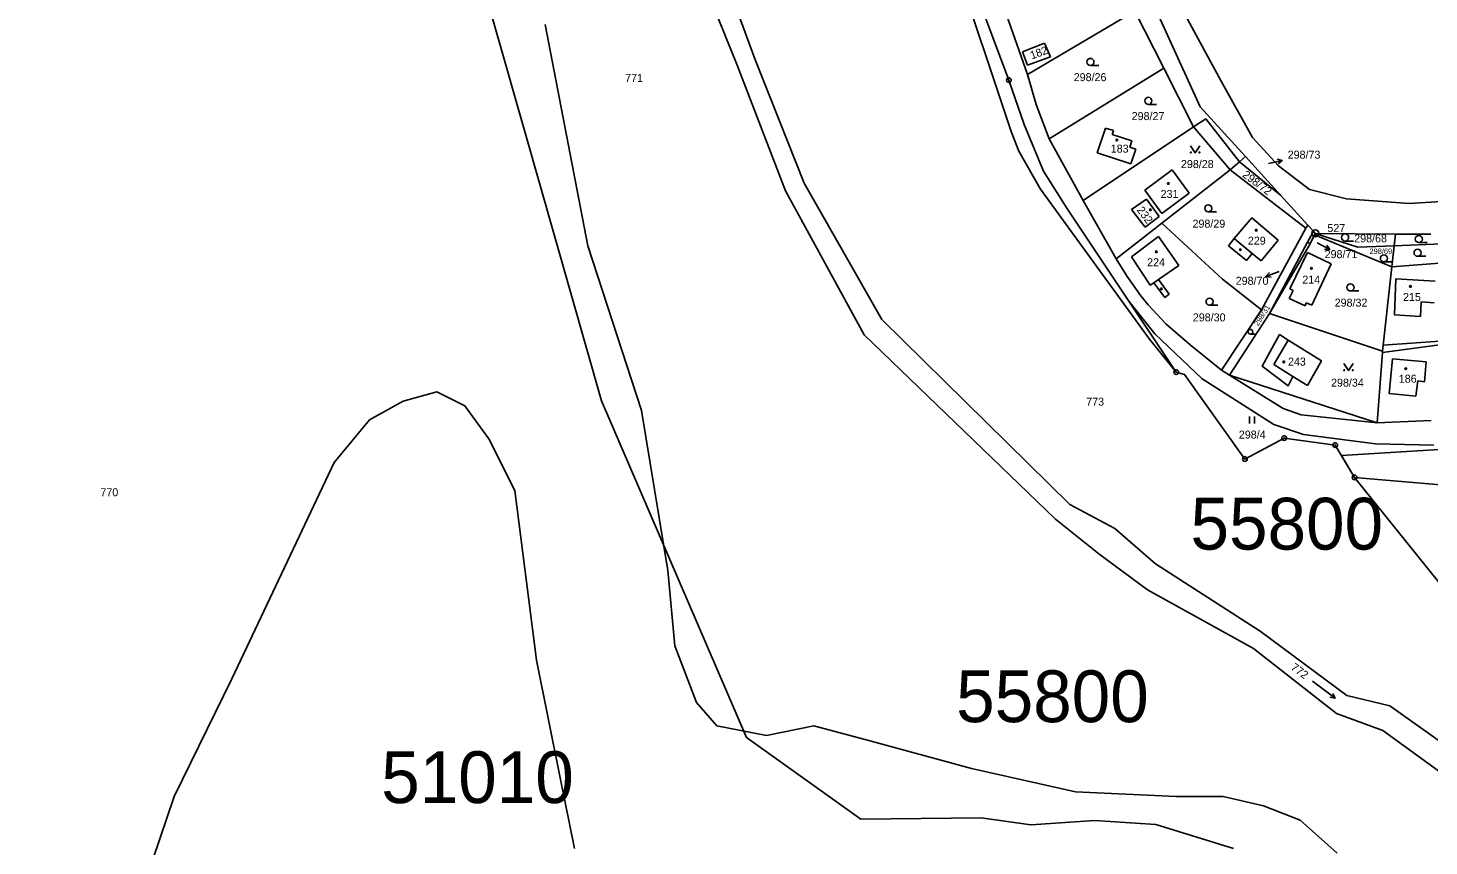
# Model space of a CAD drawing. Extents: x -725765 to -723182, y -1052705 to -1049154.
# Drawn here: x -724049.7 to -723752.1, y -1051559.5 to -1051385.7 of the extents above; entities that cross this region are included whole.
import ezdxf

# ---------------------------------------------------------------- set-up
doc = ezdxf.new("R2010")
doc.units = 0
for name, color, linetype in [('Vrstva 1', 7, 'Continuous'), ('Vrstva 16', 7, 'Continuous'), ('Vrstva 17', 7, 'Continuous'), ('Vrstva 18', 7, 'Continuous'), ('Vrstva 19', 7, 'Continuous'), ('Vrstva 25', 7, 'Continuous'), ('Vrstva 4', 7, 'Continuous'), ('Vrstva 52', 7, 'Continuous'), ('Vrstva 53', 7, 'Continuous')]:
    doc.layers.add(name, color=color, linetype=linetype)

msp = doc.modelspace()

# ---------------------------------------------------------------- linework, layer by layer
at = {"layer": 'Vrstva 1'}
for points in [[(-723911.42, -1051348.47), (-723895.29, -1051392.3)], [(-723825.2, -1051348.64), (-723800.75, -1051402.47)], [(-723899.09, -1051393.61), (-723916.43, -1051350.67)], [(-723841.35, -1051396.8), (-723855.41, -1051359.31)], [(-723944.12, -1051407.98), (-723956.41, -1051364.73)], [(-723853.14, -1051370.95), (-723840.86, -1051407.69)], [(-723844.1, -1051376.44), (-723837.44, -1051395.61)], [(-723837.44, -1051395.61), (-723814.6, -1051382.17)], [(-723814.6, -1051382.17), (-723808.48, -1051394.25)], [(-723838.46, -1051390.82), (-723833.78, -1051388.96)], [(-723833.78, -1051388.96), (-723832.5, -1051391.88)], [(-723895.29, -1051392.3), (-723884.86, -1051418.68)], [(-723838.46, -1051390.82), (-723837.38, -1051393.6)], [(-723837.38, -1051393.6), (-723832.5, -1051391.88)], [(-723888.79, -1051420.29), (-723899.09, -1051393.61)], [(-723837.44, -1051395.61), (-723835.54, -1051402)], [(-723832.83, -1051409.25), (-723808.48, -1051394.25)], [(-723808.48, -1051394.25), (-723802.14, -1051406.75)], [(-723838.11, -1051406.2), (-723841.35, -1051396.8)], [(-723835.54, -1051402), (-723832.83, -1051409.25)], [(-723800.75, -1051402.47), (-723791.11, -1051413.06)], [(-723927.86, -1051464.93), (-723944.12, -1051407.98)], [(-723839.23, -1051411.86), (-723840.86, -1051407.69)], [(-723834.01, -1051416.11), (-723838.11, -1051406.2)], [(-723825.55, -1051422.36), (-723802.14, -1051406.75)], [(-723822.62, -1051412.25), (-723820.86, -1051406.99)], [(-723820.86, -1051406.99), (-723819.12, -1051407.53)], [(-723819.39, -1051408.38), (-723819.12, -1051407.53)], [(-723802.14, -1051406.75), (-723794.39, -1051415.85)], [(-723832.83, -1051409.25), (-723825.55, -1051422.36)], [(-723819.39, -1051408.38), (-723815.24, -1051409.7)], [(-723815.65, -1051411.04), (-723815.24, -1051409.7)], [(-723815.65, -1051411.04), (-723814.42, -1051411.46)], [(-723834.66, -1051419.95), (-723839.23, -1051411.86)], [(-723822.62, -1051412.25), (-723815.48, -1051414.58)], [(-723815.48, -1051414.58), (-723814.42, -1051411.46)], [(-723792.39, -1051414.15), (-723794.39, -1051415.85)], [(-723791.11, -1051413.06), (-723792.39, -1051414.15)], [(-723792.39, -1051414.15), (-723783.68, -1051421.23)], [(-723791.11, -1051413.06), (-723783.68, -1051421.23)], [(-723829.05, -1051424.03), (-723834.01, -1051416.11)], [(-723812.51, -1051420.19), (-723806.67, -1051415.85)], [(-723808.88, -1051427.21), (-723794.39, -1051415.85)], [(-723806.67, -1051415.85), (-723803.04, -1051420.8)], [(-723794.39, -1051415.85), (-723778.28, -1051428.28)], [(-723868.34, -1051447.67), (-723884.86, -1051418.68)], [(-723811.53, -1051451.84), (-723834.66, -1051419.95)], [(-723812.51, -1051420.19), (-723808.88, -1051425.14)], [(-723872.12, -1051450.91), (-723888.79, -1051420.29)], [(-723825.55, -1051422.36), (-723818.59, -1051434.75)], [(-723815.3, -1051424.29), (-723812.11, -1051422.11)], [(-723812.11, -1051422.11), (-723809.41, -1051425.77)], [(-723808.88, -1051425.14), (-723803.04, -1051420.8)], [(-723783.68, -1051421.23), (-723777.9, -1051427.58)], [(-723829.05, -1051424.03), (-723815.9, -1051443.73)], [(-723815.3, -1051424.29), (-723812.43, -1051428.06)], [(-723812.43, -1051428.06), (-723809.41, -1051425.77)], [(-723793.5, -1051430.44), (-723789.79, -1051426.05)], [(-723789.79, -1051426.05), (-723784.18, -1051430.79)], [(-723818.59, -1051434.75), (-723808.88, -1051427.21)], [(-723808.88, -1051427.21), (-723795.99, -1051439.08)], [(-723787.69, -1051445.63), (-723778.28, -1051428.28)], [(-723777.9, -1051427.58), (-723778.28, -1051428.28)], [(-723777.9, -1051427.58), (-723776.69, -1051428.91)], [(-723776.69, -1051428.91), (-723776.9, -1051429.34)], [(-723776.69, -1051428.91), (-723776.29, -1051429.35)], [(-723815.35, -1051434.34), (-723809.58, -1051429.99)], [(-723809.58, -1051429.99), (-723805.28, -1051436.16)], [(-723794.7, -1051431.98), (-723793.5, -1051430.44)], [(-723794.7, -1051431.98), (-723790.93, -1051435.13)], [(-723787.79, -1051435.2), (-723784.18, -1051430.79)], [(-723777.93, -1051431.25), (-723785.99, -1051446.36)], [(-723785.99, -1051446.36), (-723777.34, -1051431.57)], [(-723776.9, -1051429.34), (-723777.93, -1051431.25)], [(-723777.34, -1051431.57), (-723777.93, -1051431.25)], [(-723776.45, -1051429.69), (-723777.34, -1051431.57)], [(-723776.29, -1051429.35), (-723776.45, -1051429.69)], [(-723776.45, -1051429.69), (-723760.04, -1051436.48)], [(-723776.29, -1051429.35), (-723759.26, -1051429.49)], [(-723776.29, -1051429.35), (-723767.23, -1051432.28)], [(-723767.23, -1051432.28), (-723759.54, -1051431.99)], [(-723759.54, -1051431.99), (-723760.04, -1051436.48)], [(-723759.26, -1051429.49), (-723759.54, -1051431.99)], [(-723759.54, -1051431.99), (-723749.44, -1051431.61)], [(-723759.26, -1051429.49), (-723751.73, -1051429.55)], [(-723818.59, -1051434.75), (-723816.25, -1051438.54)], [(-723815.35, -1051434.34), (-723811.32, -1051440.39)], [(-723790.93, -1051435.13), (-723789.68, -1051433.63)], [(-723789.68, -1051433.63), (-723787.79, -1051435.2)], [(-723781.68, -1051441.15), (-723777.97, -1051433.39)], [(-723777.97, -1051433.39), (-723772.88, -1051435.83)], [(-723760.04, -1051436.48), (-723736.13, -1051434.61)], [(-723809.57, -1051439.17), (-723805.28, -1051436.16)], [(-723777.02, -1051444.64), (-723772.88, -1051435.83)], [(-723761.87, -1051453.08), (-723760.04, -1051436.48)], [(-723816.25, -1051438.54), (-723813.33, -1051442.65)], [(-723811.32, -1051440.39), (-723810.6, -1051439.89)], [(-723810.6, -1051439.89), (-723808.27, -1051443.01)], [(-723809.57, -1051439.17), (-723807.3, -1051442.3)], [(-723795.99, -1051439.08), (-723787.69, -1051445.63)], [(-723759.45, -1051446.66), (-723759.19, -1051439.04)], [(-723759.19, -1051439.04), (-723750.8, -1051439.52)], [(-723815.9, -1051443.73), (-723810.33, -1051450.69)], [(-723815.9, -1051443.73), (-723805.81, -1051458.83)], [(-723813.33, -1051442.65), (-723811.81, -1051444.52)], [(-723808.27, -1051443.01), (-723807.3, -1051442.3)], [(-723781.81, -1051443.16), (-723781, -1051441.47)], [(-723781.81, -1051443.16), (-723778.47, -1051444.73)], [(-723781.68, -1051441.15), (-723781, -1051441.47)], [(-723753.96, -1051446.99), (-723753.78, -1051443.91)], [(-723753.78, -1051443.91), (-723751.05, -1051444.1)], [(-723811.81, -1051444.52), (-723808.03, -1051448.54)], [(-723796.17, -1051458.45), (-723787.69, -1051445.63)], [(-723794.52, -1051459.51), (-723785.99, -1051446.36)], [(-723785.99, -1051446.36), (-723762.01, -1051454.37)], [(-723778.47, -1051444.73), (-723778.19, -1051444.09)], [(-723778.19, -1051444.09), (-723777.02, -1051444.64)], [(-723759.45, -1051446.66), (-723753.96, -1051446.99)], [(-723828.41, -1051486.92), (-723868.34, -1051447.67)], [(-723808.03, -1051448.54), (-723802.85, -1051453.06)], [(-723831.46, -1051490.09), (-723872.12, -1051450.91)], [(-723811.53, -1051451.84), (-723805.81, -1051458.83)], [(-723810.33, -1051450.69), (-723800.28, -1051460.26)], [(-723781.05, -1051459.74), (-723782.03, -1051461.72), (-723787.55, -1051457.58), (-723783.87, -1051450.86), (-723782.02, -1051452.02)], [(-723782.02, -1051452.02), (-723774.97, -1051456.43), (-723777.96, -1051461.66)], [(-723761.87, -1051453.08), (-723737.77, -1051451.4)], [(-723802.85, -1051453.06), (-723796.17, -1051458.45)], [(-723763.16, -1051469.61), (-723762.03, -1051454.69)], [(-723762.03, -1051454.69), (-723762.01, -1051454.37)], [(-723762.01, -1051454.37), (-723761.87, -1051453.08)], [(-723804.04, -1051459.34), (-723805.81, -1051458.83)], [(-723796.17, -1051458.45), (-723794.52, -1051459.51)], [(-723760.63, -1051463.39), (-723759.92, -1051456)], [(-723759.92, -1051456), (-723752.75, -1051456.65)], [(-723753.12, -1051460.88), (-723752.75, -1051456.65)], [(-723791.24, -1051477.29), (-723804.04, -1051459.34)], [(-723800.28, -1051460.26), (-723785.11, -1051469.97)], [(-723794.52, -1051459.51), (-723763.16, -1051469.61)], [(-723777.96, -1051461.66), (-723781.05, -1051459.74)], [(-723754.9, -1051463.94), (-723754.51, -1051460.71)], [(-723754.51, -1051460.71), (-723753.12, -1051460.88)], [(-723760.63, -1051463.39), (-723754.9, -1051463.94)], [(-723927.86, -1051464.93), (-723897.11, -1051536.45)], [(-723785.11, -1051469.97), (-723778.79, -1051472.11)], [(-723763.16, -1051469.61), (-723751.71, -1051469.1)], [(-723782.91, -1051472.84), (-723791.24, -1051477.29)], [(-723782.91, -1051472.84), (-723772.04, -1051474.32)], [(-723778.79, -1051472.11), (-723763.53, -1051474.03)], [(-723767.94, -1051481.2), (-723772.04, -1051474.32)], [(-723770.72, -1051476.53), (-723730.31, -1051474.06)], [(-723770.72, -1051476.53), (-723767.94, -1051481.2)], [(-723763.53, -1051474.03), (-723751.13, -1051474.35)], [(-723767.94, -1051481.2), (-723745.73, -1051508.83)], [(-723706.54, -1051486.44), (-723767.94, -1051481.2)], [(-723818.84, -1051492.05), (-723828.41, -1051486.92)], [(-723822.26, -1051497.46), (-723831.46, -1051490.09)], [(-723810.19, -1051499.57), (-723818.84, -1051492.05)], [(-723811.9, -1051505.06), (-723822.26, -1051497.46)], [(-723787.98, -1051513.89), (-723810.19, -1051499.57)], [(-723789.38, -1051517.54), (-723811.9, -1051505.06)], [(-723769.62, -1051527.53), (-723787.98, -1051513.89)], [(-723771.8, -1051531.34), (-723789.38, -1051517.54)], [(-723760.44, -1051529.74), (-723769.62, -1051527.53)], [(-723735.81, -1051547.23), (-723760.44, -1051529.74)], [(-723761.92, -1051534.99), (-723771.8, -1051531.34)], [(-723738.43, -1051552.03), (-723761.92, -1051534.99)], [(-723897.11, -1051536.45), (-723872.8, -1051553.77)], [(-723872.8, -1051553.77), (-723847.23, -1051553.49)], [(-723847.23, -1051553.49), (-723836.69, -1051554.99)], [(-723836.69, -1051554.99), (-723823.11, -1051554.09)], [(-723823.11, -1051554.09), (-723810.14, -1051554.93)], [(-723810.14, -1051554.93), (-723793.66, -1051560.02)]]:
    msp.add_lwpolyline(points, dxfattribs=at)
at = {"layer": 'Vrstva 25'}
for points in [[(-723824.04, -1051393.68), (-723822.29, -1051393.68)], [(-723811.73, -1051401.95), (-723809.98, -1051401.95)], [(-723802.8, -1051410.76), (-723801.8, -1051412.26), (-723800.8, -1051410.76)], [(-723786.25, -1051414.5), (-723783.32, -1051413.85)], [(-723784.41, -1051413.58), (-723783.32, -1051413.85), (-723784.19, -1051414.55)], [(-723799.01, -1051424.79), (-723797.26, -1051424.79)], [(-723775.86, -1051431.39), (-723773.2, -1051432.77)], [(-723773.86, -1051431.87), (-723773.2, -1051432.77), (-723774.32, -1051432.76)], [(-723769.95, -1051430.98), (-723768.2, -1051430.98)], [(-723754.3, -1051431.31), (-723752.55, -1051431.31)], [(-723754.56, -1051434.23), (-723752.81, -1051434.23)], [(-723783.99, -1051437.47), (-723786.8, -1051438.52)], [(-723785.69, -1051438.64), (-723786.8, -1051438.52), (-723786.04, -1051437.7)], [(-723761.72, -1051435.42), (-723759.97, -1051435.42)], [(-723768.81, -1051441.59), (-723767.06, -1051441.59)], [(-723798.74, -1051444.61), (-723796.99, -1051444.61)], [(-723790.06, -1051450.76), (-723788.89, -1051450.76)], [(-723770.24, -1051457.02), (-723769.24, -1051458.52), (-723768.24, -1051457.02)], [(-723790.27, -1051469.74), (-723790.27, -1051468.24)], [(-723789.23, -1051469.74), (-723789.23, -1051468.24)], [(-723776.87, -1051524.51), (-723772.07, -1051528.11)], [(-723772.57, -1051527.11), (-723772.07, -1051528.11), (-723773.17, -1051527.91)]]:
    msp.add_lwpolyline(points, dxfattribs=at)
for centre, radius in [((-723824.04, -1051392.93), 0.75), ((-723841.35, -1051396.8), 0.5), ((-723841.35, -1051396.8), 0.032), ((-723811.73, -1051401.2), 0.75), ((-723818.42, -1051409.53), 0.175), ((-723802.7, -1051412.16), 0.1), ((-723800.9, -1051412.16), 0.1), ((-723807.5, -1051418.76), 0.175), ((-723811.32, -1051424.34), 0.175), ((-723799.01, -1051424.04), 0.75), ((-723788.84, -1051428.68), 0.175), ((-723776.29, -1051429.35), 0.75), ((-723776.29, -1051429.35), 0.032), ((-723769.95, -1051430.23), 0.75), ((-723754.3, -1051430.56), 0.75), ((-723810.03, -1051433.26), 0.175), ((-723792.19, -1051432.8), 0.175), ((-723761.72, -1051434.67), 0.75), ((-723754.56, -1051433.48), 0.75), ((-723777.1, -1051436.77), 0.175), ((-723809, -1051441.14), 0.175), ((-723768.81, -1051440.84), 0.75), ((-723756.07, -1051440.63), 0.175), ((-723798.74, -1051443.86), 0.75), ((-723790.06, -1051450.26), 0.503), ((-723805.81, -1051458.83), 0.5), ((-723805.81, -1051458.83), 0.032), ((-723782.98, -1051456.66), 0.175), ((-723770.14, -1051458.42), 0.1), ((-723768.34, -1051458.42), 0.1), ((-723757.07, -1051458.09), 0.175), ((-723782.91, -1051472.84), 0.5), ((-723782.91, -1051472.84), 0.032), ((-723772.04, -1051474.32), 0.5), ((-723772.04, -1051474.32), 0.032), ((-723791.24, -1051477.29), 0.5), ((-723791.24, -1051477.29), 0.032), ((-723767.94, -1051481.2), 0.5), ((-723767.94, -1051481.2), 0.032)]:
    msp.add_circle(centre, radius, dxfattribs=at)
at = {"layer": 'Vrstva 4'}
for points in [[(-723802.14, -1051406.75), (-723799.54, -1051405.02)], [(-723799.54, -1051405.02), (-723792.39, -1051414.15)], [(-723793.5, -1051430.44), (-723789.68, -1051433.63)], [(-723810.6, -1051439.89), (-723809.57, -1051439.17)], [(-723785.11, -1051457.21), (-723782.02, -1051452.02)], [(-723762.03, -1051454.69), (-723737.77, -1051451.4)], [(-723785.11, -1051457.21), (-723781.05, -1051459.74)], [(-723794.52, -1051459.51), (-723783.13, -1051466.53)], [(-723783.13, -1051466.53), (-723779.3, -1051467.88)], [(-723779.3, -1051467.88), (-723763.16, -1051469.61)]]:
    msp.add_lwpolyline(points, dxfattribs=at)
at = {"layer": 'Vrstva 52'}
for points in [[(-723706.54, -1051486.44), (-723767.94, -1051481.2), (-723772.04, -1051474.32), (-723782.91, -1051472.84), (-723791.24, -1051477.29), (-723804.04, -1051459.34), (-723805.81, -1051458.83), (-723815.86, -1051443.78), (-723829.05, -1051424.03), (-723834.01, -1051416.11), (-723838.11, -1051406.2), (-723841.35, -1051396.8), (-723855.41, -1051359.31), (-723866.9, -1051326.29), (-723877.25, -1051312.25), (-723881.29, -1051305.27), (-723901.66, -1051268.64), (-723911.76, -1051257.07), (-723922.07, -1051250.33), (-723939.88, -1051241.6), (-723983.42, -1051229.78), (-724003.02, -1051223.56), (-724003.58, -1051222.85)], [(-724052.94, -1051264.55), (-724048.1, -1051266.31), (-723994.84, -1051296.21), (-723962.81, -1051312.97), (-723926.39, -1051332.1), (-723911.42, -1051348.47), (-723895.29, -1051392.3), (-723884.86, -1051418.68), (-723868.34, -1051447.67), (-723828.41, -1051486.92), (-723818.84, -1051492.05), (-723810.19, -1051499.57), (-723787.98, -1051513.89), (-723769.62, -1051527.53), (-723760.44, -1051529.74), (-723735.81, -1051547.23), (-723726.68, -1051549.29), (-723706.61, -1051583.2)], [(-724050.47, -1051269.54), (-723997.26, -1051299.64), (-723964.68, -1051317.59), (-723929.12, -1051336.03), (-723916.43, -1051350.67), (-723899.09, -1051393.61), (-723888.79, -1051420.29), (-723872.12, -1051450.91), (-723831.46, -1051490.09), (-723822.26, -1051497.46), (-723811.9, -1051505.06), (-723789.38, -1051517.54), (-723771.8, -1051531.34), (-723761.92, -1051534.99), (-723738.43, -1051552.03), (-723728.55, -1051554.37), (-723711.06, -1051586.5), (-723687.84, -1051594.09), (-723669.45, -1051611.26), (-723662.6, -1051628), (-723652.76, -1051646.8), (-723641.04, -1051681.92), (-723643.18, -1051682.48), (-723641.32, -1051689.61)], [(-723797.67, -1051320.64), (-723794.81, -1051326.76), (-723811.35, -1051338.44), (-723823.52, -1051347.4), (-723813.63, -1051365), (-723796.31, -1051397), (-723789.63, -1051409), (-723784.13, -1051415), (-723777.5, -1051420), (-723769.69, -1051422), (-723756.38, -1051423), (-723740.38, -1051422), (-723724.38, -1051420), (-723698.63, -1051414), (-723674.63, -1051408), (-723658.19, -1051405), (-723642.02, -1051404.66)], [(-723939.81, -1051385), (-723930.81, -1051432), (-723919.38, -1051467), (-723913.81, -1051501), (-723912.31, -1051517), (-723907.69, -1051529), (-723903.38, -1051534), (-723892.81, -1051536), (-723882.81, -1051534), (-723871.38, -1051537), (-723849.31, -1051543), (-723827.19, -1051548), (-723805.81, -1051549), (-723795.88, -1051549), (-723787.31, -1051551), (-723779.5, -1051554), (-723771.63, -1051561)], [(-723933.63, -1051560), (-723936.63, -1051545), (-723941.69, -1051520), (-723946.31, -1051484), (-723951.81, -1051473), (-723956.88, -1051466), (-723962.88, -1051463), (-723970, -1051465), (-723977.13, -1051469), (-723984.69, -1051478), (-724006.38, -1051524), (-724018.63, -1051549), (-724024.69, -1051567)]]:
    msp.add_lwpolyline(points, dxfattribs=at)

# ---------------------------------------------------------------- texts
at = {"layer": 'Vrstva 16'}
for s, p in [('298/73', (-723782.15, -1051413.49)), ('298/71', (-723774.3, -1051434.62)), ('298/70', (-723793.19, -1051440.28))]:
    msp.add_text(s, height=1.7, dxfattribs=at).set_placement(p)
at = {"layer": 'Vrstva 17'}
msp.add_text('527 ', height=1.7, dxfattribs=at).set_placement((-723773.72, -1051429.08))
at = {"layer": 'Vrstva 18'}
for s, height, p in [('771', 1.7, (-723922.86, -1051397.17)), ('298/26', 1.7, (-723827.59, -1051397.02)), ('298/27', 1.7, (-723815.28, -1051405.29)), ('298/28', 1.7, (-723804.82, -1051415.48)), ('298/73', 0.1, (-723790.23, -1051415.18)), ('298/29', 1.7, (-723802.36, -1051428.14)), ('298/71', 0.1, (-723777.26, -1051430.48)), ('298/68', 1.7, (-723768.02, -1051431.27)), ('298/69', 1.14, (-723764.77, -1051433.72)), ('298/70', 0.1, (-723780.11, -1051435.83)), ('298/32', 1.7, (-723772.17, -1051444.92)), ('298/30', 1.7, (-723802.29, -1051448.05)), ('298/34', 1.7, (-723772.94, -1051461.92)), ('773', 1.7, (-723824.94, -1051465.96)), ('298/4', 1.7, (-723792.52, -1051472.95)), ('770', 1.7, (-724034.3, -1051485.2))]:
    msp.add_text(s, height=height, dxfattribs=at).set_placement(p)
for s, height, rotation, p in [('298/72', 1.7, 323.1026, (-723791.9, -1051417.2)), ('298/31', 1.19, 57.4005, (-723788.41, -1051449.12)), ('772', 1.7, 323.1026, (-723781.61, -1051521.86))]:
    msp.add_text(s, height=height, rotation=rotation, dxfattribs=at).set_placement(p)
at = {"layer": 'Vrstva 19'}
for s, rotation, p in [('182', 20.0002, (-723836.49, -1051392.41)), ('232', 306.8024, (-723814.28, -1051424.42))]:
    msp.add_text(s, height=1.7, rotation=rotation, dxfattribs=at).set_placement(p)
for s, p in [('183', (-723819.73, -1051412.2)), ('231', (-723809.14, -1051421.84)), ('229', (-723790.61, -1051431.76)), ('224', (-723812, -1051436.34)), ('214', (-723779.05, -1051440.03)), ('215', (-723757.66, -1051443.72)), ('243', (-723782.09, -1051457.44)), ('186', (-723758.55, -1051461.08))]:
    msp.add_text(s, height=1.7, dxfattribs=at).set_placement(p)
at = {"layer": 'Vrstva 53'}
for s, p in [('55800', (-723802.79, -1051496.53)), ('55800', (-723852.56, -1051533.19)), ('51010', (-723974.67, -1051550.38))]:
    msp.add_text(s, height=11, dxfattribs=at).set_placement(p)

doc.saveas('drawing.dxf')
